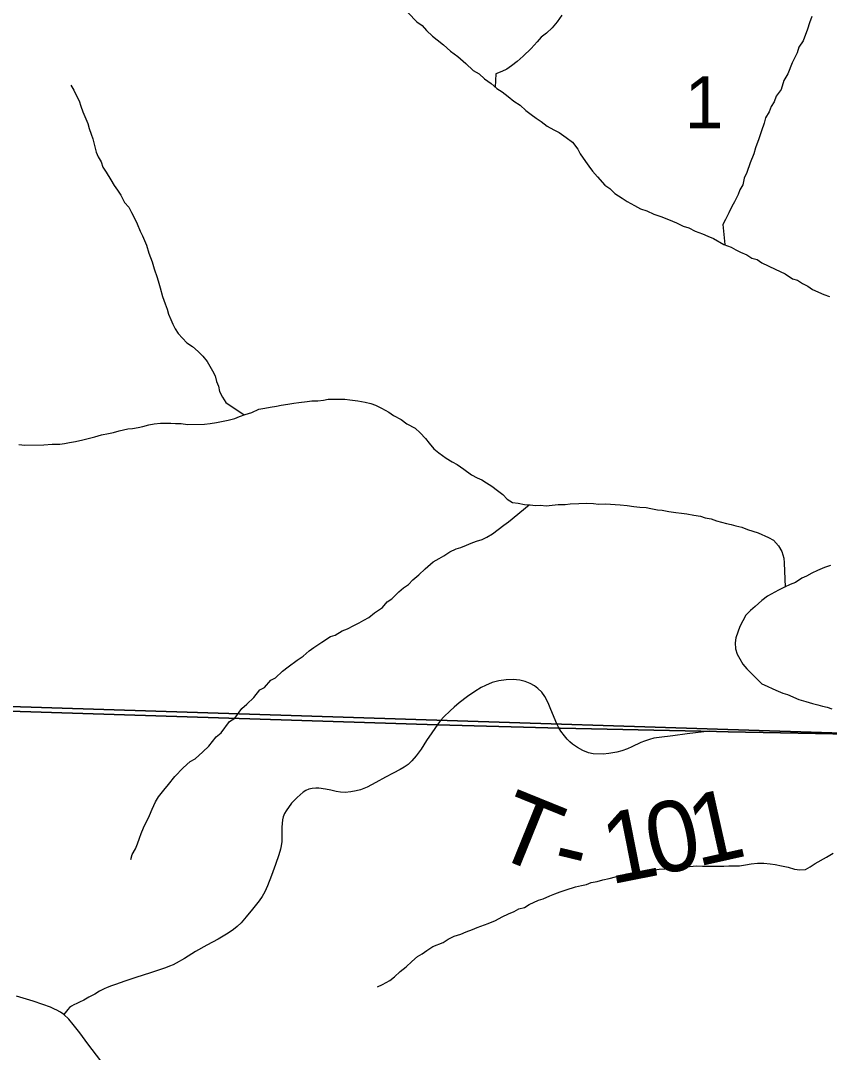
# Model space of a CAD drawing. Extents: x -3.3 to 34, y 0 to 56.8.
# Drawn here: x 0.833 to 1.485, y 33.346 to 34.177 of the extents above; entities that cross this region are included whole.
import ezdxf

# ---------------------------------------------------------------- set-up
doc = ezdxf.new("R2010")
doc.units = 0
for name, color, linetype in [('GM_X_Corporation', 7, 'Continuous'), ('GM_X_County_Road', 7, 'Continuous'), ('GM_X_Section_Text', 7, 'Continuous'), ('GM_X_Township_Road', 7, 'Continuous'), ('GM_X_Township_Road_Text', 7, 'Continuous'), ('GT_Project_Soil_Layers', 7, 'Continuous')]:
    doc.layers.add(name, color=color, linetype=linetype)

msp = doc.modelspace()

# ---------------------------------------------------------------- linework, layer by layer
at = {"layer": 'GM_X_Corporation'}
for points in [[(1.84017, 34.87705), (-3.30393, 34.87705), (-3.30393, 33.7379), (-1.95594, 33.69761), (-1.4178, 33.68276), (-1.31578, 33.67985), (-1.26472, 33.67853), (-1.26192, 33.67846), (-1.25588, 33.6783), (-1.24768, 33.67809), (-0.68402, 33.66353), (0.07113, 33.6404), (0.53861, 33.62974), (1.16908, 33.60969), (1.26798, 33.60697), (1.38132, 33.6045), (1.39386, 33.60423), (1.40335, 33.60404), (1.51565, 33.60182), (1.54523, 33.60124), (1.79797, 33.59224), (1.81648, 34.17132), (1.8337, 34.72257), (1.83943, 34.85654)], [(0.80707, 34.64081), (1.83091, 34.60519), (1.82548, 34.44632), (1.79698, 33.59314), (0.77432, 33.62613)], [(1.79698, 33.59314), (1.79067, 33.44183), (1.75705, 32.57759), (0.73569, 32.62424), (0.77432, 33.62613)]]:
    msp.add_lwpolyline(points, close=True, dxfattribs=at)
msp.add_lwpolyline([(1.69805, 31.56614), (1.74587, 32.36303), (1.74609, 32.36849), (1.74848, 32.4264), (1.74928, 32.44591), (1.75537, 32.59405), (1.75808, 32.65987), (1.75838, 32.6672), (1.7602, 32.71145), (1.78315, 33.26936), (1.79014, 33.43939), (1.79797, 33.59224), (1.54523, 33.60124), (1.51565, 33.60182), (1.40335, 33.60404), (1.39386, 33.60423), (1.38132, 33.6045), (1.26798, 33.60697), (1.16908, 33.60969), (0.53861, 33.62974), (0.07113, 33.6404), (-0.68402, 33.66353)], dxfattribs=at)
at = {"layer": 'GM_X_County_Road'}
for points in [[(0.86208, 33.38007), (0.86124, 33.38051), (0.85746, 33.38224), (0.85129, 33.38454), (0.8434, 33.38725), (0.82992, 33.39128)], [(0.90135, 33.33465), (0.88746, 33.35273), (0.88105, 33.36153), (0.8757, 33.36843), (0.87217, 33.37271), (0.86812, 33.37643), (0.86543, 33.37829), (0.86208, 33.38007)]]:
    msp.add_lwpolyline(points, dxfattribs=at)
at = {"layer": 'GM_X_Township_Road'}
for points in [[(1.26527, 33.61036), (1.26048, 33.62201), (1.25815, 33.62739), (1.2555, 33.63251), (1.2532, 33.63585), (1.25007, 33.63875), (1.24717, 33.64099), (1.24368, 33.64289), (1.23976, 33.64449), (1.23558, 33.64547), (1.23012, 33.64606), (1.22454, 33.64595), (1.21846, 33.64516), (1.21315, 33.64378), (1.20781, 33.64142), (1.20437, 33.63963), (1.19933, 33.63656), (1.19337, 33.63241), (1.18671, 33.62735), (1.18246, 33.62388), (1.17921, 33.62096), (1.17429, 33.61611), (1.1714, 33.61275)], [(1.1714, 33.61275), (1.1604, 33.59696), (1.15584, 33.59), (1.15198, 33.58456), (1.1485, 33.58073), (1.14542, 33.57781), (1.14227, 33.57555), (1.13902, 33.57363), (1.13343, 33.57062), (1.12734, 33.56737), (1.11933, 33.56312), (1.11241, 33.55945), (1.10716, 33.55736), (1.10349, 33.55636), (1.0994, 33.55561), (1.09481, 33.55528), (1.09098, 33.55553), (1.08739, 33.55603), (1.08314, 33.55695), (1.07889, 33.5577), (1.07347, 33.55853), (1.07113, 33.55861), (1.06804, 33.55828), (1.06538, 33.5577), (1.06304, 33.5567), (1.06104, 33.55544), (1.0562, 33.55119), (1.05161, 33.54652), (1.04711, 33.54043), (1.04586, 33.53818), (1.04494, 33.5356), (1.04436, 33.53301), (1.04394, 33.53018), (1.04377, 33.52734), (1.04369, 33.52442), (1.04377, 33.52009), (1.04361, 33.51558), (1.04328, 33.51225), (1.04269, 33.50941), (1.04142, 33.50501), (1.03869, 33.49715), (1.03552, 33.48831), (1.03216, 33.47994), (1.03005, 33.4752), (1.02801, 33.47147), (1.02543, 33.46787), (1.02015, 33.46109), (1.01503, 33.45504), (1.01091, 33.45023), (1.00785, 33.44717), (1.00491, 33.44495), (1.00048, 33.44182), (0.99232, 33.43708), (0.98343, 33.43216), (0.97417, 33.42701), (0.96521, 33.42141), (0.9586, 33.41766), (0.95629, 33.41642), (0.95337, 33.41525), (0.95003, 33.41408), (0.93783, 33.40998), (0.92625, 33.40617), (0.91714, 33.40318), (0.90973, 33.40059), (0.90659, 33.39947), (0.90293, 33.39806), (0.90053, 33.39698), (0.89692, 33.39511), (0.893, 33.39286), (0.88834, 33.39028), (0.88417, 33.38784), (0.88069, 33.3862), (0.87849, 33.38521), (0.87624, 33.38418), (0.87436, 33.38314), (0.87277, 33.38193), (0.87131, 33.38042), (0.86812, 33.37643)], [(1.38813, 33.60465), (1.37017, 33.60229), (1.35865, 33.60085), (1.34768, 33.59941), (1.34347, 33.59878), (1.33977, 33.59776), (1.33593, 33.59655), (1.33291, 33.5953), (1.32556, 33.59187), (1.32208, 33.59018), (1.31749, 33.58868), (1.31362, 33.58751), (1.30714, 33.58643), (1.30247, 33.58601), (1.29455, 33.58634), (1.29088, 33.58718), (1.28621, 33.58893), (1.28187, 33.59127), (1.27778, 33.5941), (1.27561, 33.59602), (1.2737, 33.59802), (1.27144, 33.60077), (1.26854, 33.60466), (1.26694, 33.60728), (1.26527, 33.61036)]]:
    msp.add_lwpolyline(points, dxfattribs=at)
at = {"layer": 'GT_Project_Soil_Layers'}
for points in [[(1.14556, 34.18282), (1.15248, 34.1757), (1.15669, 34.17272), (1.16016, 34.1686), (1.16515, 34.16411), (1.16898, 34.16113), (1.17397, 34.15702), (1.17972, 34.15216), (1.18547, 34.14768), (1.19199, 34.14208), (1.19776, 34.13647), (1.20272, 34.13388), (1.20695, 34.12976), (1.21231, 34.12604), (1.21691, 34.12192), (1.22112, 34.11932), (1.2261, 34.1156), (1.2307, 34.11186), (1.23568, 34.10852), (1.24028, 34.1044), (1.2445, 34.10104), (1.24871, 34.09807), (1.25254, 34.09546), (1.25752, 34.09173), (1.26287, 34.08877), (1.26707, 34.08655), (1.27281, 34.08245), (1.27779, 34.07872), (1.28204, 34.07309), (1.28398, 34.06932), (1.28824, 34.0633), (1.29094, 34.05954), (1.29403, 34.05541), (1.29788, 34.05091), (1.30404, 34.04416), (1.30787, 34.04155), (1.3121, 34.03744), (1.31784, 34.03372), (1.32204, 34.03112), (1.32778, 34.02778), (1.33274, 34.02519), (1.33769, 34.02336), (1.34342, 34.02078), (1.34913, 34.01896), (1.35523, 34.01639), (1.36171, 34.01382), (1.36706, 34.01124), (1.37162, 34.00978), (1.37659, 34.00719), (1.38269, 34.005), (1.38688, 34.00316), (1.39146, 34.00132), (1.39987, 33.9965), (1.40558, 33.9943), (1.40941, 33.99208), (1.41322, 33.99023), (1.41818, 33.98802), (1.42239, 33.98542), (1.42657, 33.98434), (1.4304, 33.98174), (1.44109, 33.97657), (1.44528, 33.97473), (1.4491, 33.97288), (1.45522, 33.96879), (1.45903, 33.9677), (1.46324, 33.9651), (1.46744, 33.96288), (1.47126, 33.96028), (1.48042, 33.95623)], [(1.26919, 34.18111), (1.26548, 34.17574), (1.26137, 34.17075), (1.25688, 34.16651), (1.25275, 34.16342), (1.24939, 34.15958), (1.24453, 34.15419), (1.23817, 34.14803), (1.2333, 34.14379), (1.2288, 34.14031), (1.22504, 34.1376), (1.2209, 34.13565), (1.216, 34.13368), (1.21558, 34.12312)], [(1.47055, 34.18008), (1.46873, 34.17474), (1.46728, 34.16979), (1.46362, 34.16025), (1.46027, 34.15527), (1.45882, 34.15069), (1.4566, 34.14648), (1.45475, 34.14266), (1.45146, 34.13389), (1.44812, 34.12853), (1.44594, 34.12128), (1.44184, 34.11591), (1.44039, 34.11134), (1.43779, 34.1075), (1.43633, 34.10331), (1.43336, 34.09833), (1.43228, 34.09414), (1.43009, 34.08803), (1.42791, 34.08155), (1.42535, 34.0743), (1.4239, 34.06935), (1.42096, 34.06209), (1.41841, 34.05446), (1.4162, 34.04988), (1.41514, 34.04455), (1.41254, 34.04034), (1.41145, 34.03653), (1.4085, 34.03079), (1.40628, 34.02696), (1.40369, 34.02199), (1.40111, 34.01664), (1.39889, 34.01243), (1.40052, 33.99625)], [(0.87373, 34.12477), (0.87606, 34.12063), (0.87839, 34.11611), (0.88035, 34.11196), (0.88192, 34.1078), (0.8835, 34.10327), (0.88742, 34.09383), (0.88861, 34.08967), (0.89019, 34.08514), (0.89138, 34.08136), (0.89418, 34.07077), (0.89575, 34.06699), (0.89808, 34.06285), (0.89965, 34.05869), (0.90236, 34.05455), (0.90586, 34.04853), (0.90857, 34.04401), (0.91128, 34.04025), (0.91399, 34.03611), (0.9171, 34.03008), (0.92057, 34.02633), (0.92252, 34.02218), (0.92485, 34.01803), (0.92719, 34.01313), (0.92955, 34.00709), (0.9315, 34.00332), (0.93463, 33.99577), (0.93662, 33.98934), (0.93936, 33.98255), (0.94096, 33.97687), (0.94333, 33.96969), (0.94453, 33.96515), (0.94572, 33.96137), (0.94771, 33.95456), (0.94969, 33.94851), (0.95126, 33.94436), (0.95245, 33.9402), (0.95441, 33.93605), (0.95598, 33.93228), (0.95792, 33.9285), (0.96025, 33.92474), (0.96371, 33.92099), (0.96717, 33.91724), (0.97176, 33.91427), (0.97637, 33.91015), (0.98021, 33.90641), (0.98368, 33.90228), (0.98563, 33.89851), (0.98796, 33.89475), (0.98991, 33.8906), (0.99111, 33.88606), (0.99268, 33.88228), (0.99349, 33.87811), (0.99583, 33.87359), (0.99855, 33.86907), (1.01332, 33.8591)], [(1.48042, 33.95623), (1.485, 33.95439)], [(0.86478, 33.8357), (0.86856, 33.83613), (0.87272, 33.83695), (0.87764, 33.83777), (0.88331, 33.83899), (0.89314, 33.84141), (0.89842, 33.843), (0.90409, 33.84422), (0.90825, 33.84503), (0.91279, 33.84624), (0.91959, 33.84785), (0.92337, 33.84828), (0.92791, 33.8491), (0.93169, 33.84992), (0.93661, 33.85112), (0.94077, 33.85194), (0.94607, 33.85239), (0.95441, 33.85251), (0.95821, 33.85218), (0.96276, 33.85225), (0.96769, 33.85155), (0.98134, 33.85174), (0.98589, 33.85219), (0.99118, 33.85302), (0.99647, 33.85423), (1.00063, 33.85505), (1.00593, 33.85626), (1.00969, 33.85783), (1.01422, 33.85942), (1.01951, 33.86101), (1.02516, 33.86374), (1.03008, 33.86457), (1.03424, 33.86539), (1.03954, 33.86622), (1.04332, 33.86703), (1.04861, 33.86786), (1.05353, 33.86869), (1.05732, 33.86913), (1.06413, 33.86998), (1.06792, 33.87041), (1.07284, 33.87048), (1.07739, 33.87092), (1.08117, 33.87173), (1.09444, 33.87192), (1.09862, 33.87121), (1.10507, 33.87055), (1.11077, 33.86949), (1.11534, 33.86841), (1.11915, 33.86694), (1.12411, 33.86473), (1.12984, 33.86139), (1.13367, 33.85879), (1.13978, 33.85546), (1.14438, 33.8521), (1.15125, 33.8484), (1.1551, 33.84466), (1.15933, 33.84016), (1.16241, 33.8364), (1.16627, 33.8319), (1.17011, 33.82853), (1.17623, 33.82444), (1.18082, 33.82147), (1.18502, 33.81925), (1.19038, 33.81552), (1.19651, 33.81105), (1.20109, 33.80846), (1.20491, 33.80699), (1.20873, 33.80438), (1.21294, 33.80178), (1.21754, 33.79843), (1.22175, 33.79507), (1.22522, 33.79132), (1.22942, 33.78872), (1.23398, 33.78802), (1.23931, 33.78696), (1.24386, 33.78664), (1.24803, 33.78632), (1.2522, 33.78638), (1.25676, 33.78606), (1.26623, 33.78695), (1.27191, 33.78703), (1.27608, 33.78746), (1.2829, 33.78794), (1.28896, 33.78802), (1.29466, 33.78772), (1.29883, 33.7874), (1.30451, 33.78748), (1.31628, 33.78688), (1.32198, 33.7862), (1.32729, 33.78552), (1.33223, 33.78482), (1.33717, 33.78451), (1.34097, 33.7838), (1.34629, 33.78274), (1.35009, 33.78241), (1.35541, 33.78135), (1.36111, 33.78066), (1.36566, 33.77997), (1.36984, 33.77965), (1.37554, 33.77858), (1.38087, 33.77752)], [(0.8318, 33.83524), (0.83673, 33.83493), (0.85189, 33.83514), (0.85871, 33.83561), (0.86478, 33.8357)], [(0.92208, 33.50111), (0.92316, 33.5053), (0.92575, 33.5099), (0.92759, 33.51372), (0.92905, 33.5183), (0.93051, 33.52212), (0.93234, 33.52671), (0.93714, 33.53665), (0.93934, 33.54162), (0.94191, 33.54773), (0.94451, 33.55157), (0.94861, 33.55694), (0.95234, 33.56155), (0.95756, 33.56808), (0.96429, 33.57501), (0.96991, 33.58003), (0.97404, 33.58236), (0.98004, 33.58776), (0.9849, 33.59239), (0.99086, 33.60007), (0.99499, 33.60317), (1.00169, 33.61238), (1.00582, 33.61509), (1.01141, 33.62277), (1.01553, 33.62624), (1.02114, 33.63164), (1.02599, 33.63778), (1.02975, 33.63973), (1.03498, 33.6455), (1.03874, 33.64746), (1.04436, 33.65285), (1.04886, 33.65633), (1.05599, 33.66175), (1.06088, 33.66485), (1.06575, 33.6691), (1.0695, 33.67181), (1.07589, 33.67608), (1.08303, 33.68073), (1.0868, 33.68192), (1.09244, 33.68542), (1.09659, 33.687), (1.10186, 33.68973), (1.10601, 33.69169), (1.10977, 33.69402), (1.11391, 33.69597), (1.11841, 33.69983), (1.1248, 33.7041), (1.12852, 33.70871), (1.13228, 33.71104), (1.13789, 33.71681), (1.14164, 33.7199), (1.14577, 33.72262), (1.14913, 33.72646), (1.15401, 33.73033), (1.15925, 33.73534), (1.16562, 33.74075), (1.17051, 33.74347), (1.17427, 33.7458), (1.17916, 33.74891), (1.18406, 33.75125), (1.18783, 33.75245), (1.19236, 33.75441), (1.19613, 33.75598), (1.20065, 33.75756), (1.20519, 33.75876), (1.20895, 33.76071), (1.21346, 33.76343), (1.22247, 33.77039), (1.22622, 33.7731), (1.2431, 33.78669)], [(1.38087, 33.77752), (1.38467, 33.77643), (1.38962, 33.77536), (1.39381, 33.7739), (1.39799, 33.77282), (1.4018, 33.77173), (1.4056, 33.77103), (1.40941, 33.76994), (1.41435, 33.76887), (1.41893, 33.76703), (1.42731, 33.76411), (1.4357, 33.76042), (1.4399, 33.75821), (1.44376, 33.7537), (1.44647, 33.74918), (1.44806, 33.74389), (1.44849, 33.7401), (1.44922, 33.72058)], [(1.48568, 33.73795), (1.48077, 33.73636), (1.47512, 33.734), (1.4706, 33.73167), (1.46646, 33.72933), (1.46269, 33.72776), (1.45743, 33.72427), (1.45328, 33.72269), (1.44876, 33.72035), (1.44387, 33.718), (1.43483, 33.71332), (1.43033, 33.70984), (1.42509, 33.70483), (1.42134, 33.70174), (1.4176, 33.69789), (1.41501, 33.6933), (1.4128, 33.68871), (1.41097, 33.68413), (1.40951, 33.67955), (1.40881, 33.67574), (1.40925, 33.67081), (1.41045, 33.66665), (1.41277, 33.66288), (1.41511, 33.65836), (1.4182, 33.6546), (1.4305, 33.64262), (1.43469, 33.64077), (1.43927, 33.63856), (1.44347, 33.63672), (1.44728, 33.63525), (1.45109, 33.63416), (1.46024, 33.63011), (1.46596, 33.62829), (1.47129, 33.62685), (1.47547, 33.62576), (1.47928, 33.62467), (1.48308, 33.62397), (1.48689, 33.6225)], [(1.12067, 33.39863), (1.12481, 33.40059), (1.13083, 33.40371), (1.13458, 33.4068), (1.13908, 33.41104), (1.14395, 33.41491), (1.14844, 33.41915), (1.15294, 33.42301), (1.1567, 33.42534), (1.16045, 33.42805), (1.16534, 33.43116), (1.17364, 33.43431), (1.17777, 33.43703), (1.18267, 33.43938), (1.18796, 33.44097), (1.1921, 33.44293), (1.19738, 33.4449), (1.20115, 33.44647), (1.20983, 33.44963), (1.21586, 33.45199), (1.22112, 33.4551), (1.2264, 33.45746), (1.23092, 33.45942), (1.23469, 33.46137), (1.23922, 33.46257), (1.24298, 33.46491), (1.25052, 33.46843), (1.25429, 33.46962), (1.25957, 33.47197), (1.26372, 33.47355), (1.26787, 33.47513), (1.27277, 33.47671), (1.28033, 33.4791), (1.28524, 33.48031), (1.28902, 33.48112), (1.29279, 33.48269), (1.29771, 33.48352), (1.30224, 33.48472), (1.30753, 33.48593), (1.31244, 33.48714), (1.3166, 33.48834), (1.32151, 33.48954), (1.32567, 33.49036), (1.32946, 33.49079), (1.33324, 33.49123), (1.33816, 33.49205), (1.34383, 33.49289), (1.34762, 33.49332), (1.35255, 33.49377), (1.35746, 33.4946), (1.36844, 33.49551), (1.37224, 33.49556), (1.37792, 33.49602), (1.38247, 33.49571), (1.39991, 33.49595), (1.4037, 33.496), (1.41242, 33.49612), (1.41734, 33.49695), (1.42188, 33.49777), (1.4268, 33.49822), (1.43211, 33.49829), (1.43705, 33.4976), (1.44122, 33.49728), (1.44617, 33.4962), (1.45149, 33.49514), (1.45682, 33.49331), (1.461, 33.49299), (1.46555, 33.49305), (1.46931, 33.49538), (1.47344, 33.4981), (1.48247, 33.50316), (1.48774, 33.50627)]]:
    msp.add_lwpolyline(points, dxfattribs=at)

# ---------------------------------------------------------------- texts
at = {"layer": 'GM_X_Section_Text'}
msp.add_text('1', height=0.04186, rotation=0.00001, dxfattribs=at).set_placement((1.36826, 34.08994))
at = {"layer": 'GM_X_Township_Road_Text'}
for s, rotation, p in [('T', 337.94155, (1.21094, 33.50579)), ('1', 12.62654, (1.3784, 33.4953)), ('0', 11.901, (1.34339, 33.48792)), ('1', 11.16516, (1.30828, 33.48099)), ('-', 346.41433, (1.25904, 33.48702))]:
    msp.add_text(s, height=0.05682, rotation=rotation, dxfattribs=at).set_placement(p)

doc.saveas('drawing.dxf')
